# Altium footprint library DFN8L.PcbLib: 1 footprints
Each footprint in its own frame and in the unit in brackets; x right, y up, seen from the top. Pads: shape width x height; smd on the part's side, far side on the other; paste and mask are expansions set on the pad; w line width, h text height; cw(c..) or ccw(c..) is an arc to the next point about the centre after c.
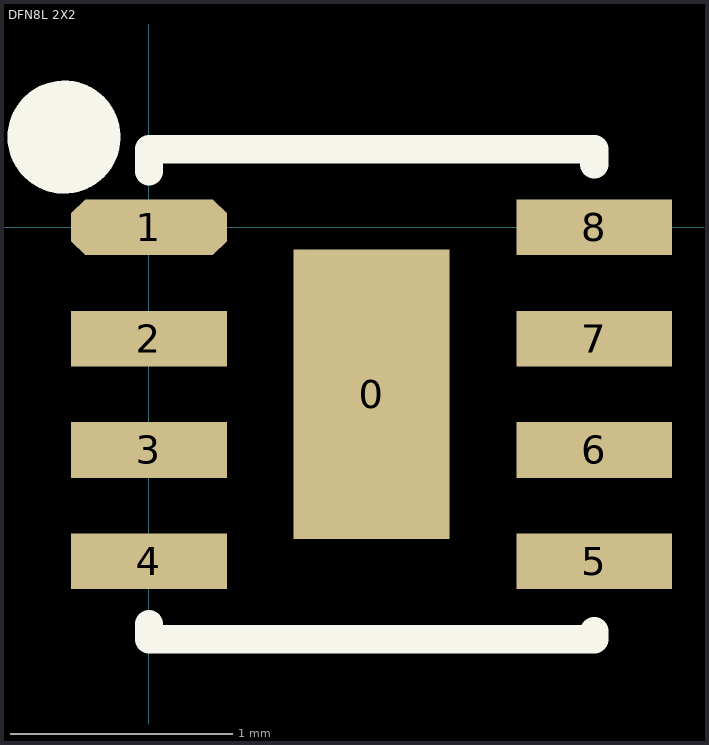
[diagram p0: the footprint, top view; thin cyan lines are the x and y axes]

## DFN8L 2X2 [mm]
pads (9):
  rect 0.7x1.3 smd: 0(1,-0.75)
  oct 0.7x0.25 smd: 1(0,0)
  rect 0.7x0.25 smd: 2(0,-0.5) 3(0,-1) 4(0,-1.5) 5(2,-1.5) 6(2,-1) 7(2,-0.5) 8(2,0)
Top Overlay:
  circle w0.254: c-0.381,0.405 r0.127
  lines w0.127: 0,-1.782 0,-1.85 2,-1.85 2,-1.814 ; 0,0.25 0,0.35 2,0.35 2,0.282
